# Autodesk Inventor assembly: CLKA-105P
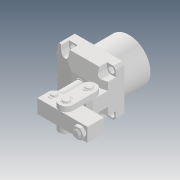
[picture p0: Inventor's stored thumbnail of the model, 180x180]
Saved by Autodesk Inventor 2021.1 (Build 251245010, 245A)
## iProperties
Created: 2018-07
Part Number: CLKA-105P
Description: STEP AP203
Document SubType Name: Assembly
Designer: user
Title: CLKA-105P.STEP
Revision Number: ÈÎºÎ
Sending System: SolidWorks 2015
Preprocessor: SwSTEP 2.0
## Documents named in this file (11)
- D:\Vault_2016\Projekty\Clamptek\Hydraulic\CLKA-P\Inventor\CLKA-105P\CLKA-105P.iam
- D:\Vault_2016\Projekty\Clamptek\Hydraulic\CLKA-P\Inventor\CLKA-105P\CLKA-105P-benti.ipt
- D:\Vault_2016\Projekty\Clamptek\Hydraulic\CLKA-P\Inventor\CLKA-105P\duanxiao105.ipt
- D:\Vault_2016\Projekty\Clamptek\Hydraulic\CLKA-P\Inventor\CLKA-105P\kahuang01.ipt
- D:\Vault_2016\Projekty\Clamptek\Hydraulic\CLKA-P\Inventor\CLKA-105P\liangan105.ipt
- D:\Vault_2016\Projekty\Clamptek\Hydraulic\CLKA-P\Inventor\CLKA-105P\luomu105.ipt
- D:\Vault_2016\Projekty\Clamptek\Hydraulic\CLKA-P\Inventor\CLKA-105P\luosi105.ipt
- D:\Vault_2016\Projekty\Clamptek\Hydraulic\CLKA-P\Inventor\CLKA-105P\yabi105.ipt
- D:\Vault_2016\Projekty\Clamptek\Hydraulic\CLKA-P\Inventor\CLKA-105P\zhangxiao105.ipt
- D:\Vault_2016\Projekty\Clamptek\Hydraulic\CLKA-P\Inventor\CLKA-105P\kahuang02.ipt
- D:\Vault_2016\Projekty\Clamptek\Hydraulic\CLKA-P\Inventor\CLKA-105P\¶ÂÍ·G8-3.ipt
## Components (17 placed, 17 different names)
1. CLKA-105P-benti_1
2. duanxiao105_2
3. kahuang01_3
4. liangan105_4
5. luomu105_5
6. luosi105_6
7. yabi105_7
8. zhangxiao105_8
9. liangan105_9
10. zhangxiao105_10
11. kahuang01_11
12. kahuang01_12
13. kahuang01_13
14. kahuang02_14
15. kahuang02_15
16. ¶ÂÍ·G8-3_16
17. ¶ÂÍ·G8-3_17
